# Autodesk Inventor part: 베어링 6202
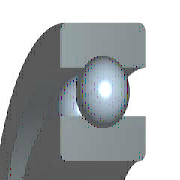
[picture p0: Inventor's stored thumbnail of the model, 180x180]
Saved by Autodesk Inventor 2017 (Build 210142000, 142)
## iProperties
IsCustomPart: 1
Created: 2015-12
Part Number: 베어링 6202
Material: 강철, 연강
Description: 깊은 그루브 볼 베어링
Document SubType Name: Modeling
Standard: KS B 2023
Designer: mdu
Standards Organization: KS
Language: ko-KR
Size Designation: 6202 - 15 x 35 x 11
Categories: <MemberInstance><Categories><Category DisplayName="샤프트 부품" InternalName="7f7aeb1f-a693-4053-b835-cee3144e0d98" Mnemonic="SHFT"><Category DisplayName="베어링" Inter
Density: 7.86 g/cm^3
Mass: 45.8725 g
Surface Area: 51.5584 cm^2
Volume: 5.83619 cm^3
Appearance: 노란색
Author: mdu
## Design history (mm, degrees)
sketch "스케치" dims "d0" = 5.2 (= -0.26 x WD + 0.26 x BD)
  geometry: L1 (2.9, 12.5)-(8.1, 12.5); L2 (5.5, 12.5)-(5.5, 9.9); L3 (5.5, 12.5)-(5.5, 15.1); L4 (3.568, 10.76)-(0, 10.76); L5 (0, 7.5)-(11, 7.5); L6 (3.568, 14.24)-(0, 14.24); L7 (0, 17.5)-(11, 17.5); L8 (11, 7.5)-(11, 10.76); L9 (7.432, 10.76)-(11, 10.76); L10 (7.432, 14.24)-(11, 14.24); L11 (11, 17.5)-(11, 14.24); L12 (-1.4, 0)-(8.4, 0) reference; L13 (0, -0.3)-(0, 5.3) reference
  constraints: 22 end point, 4 point on line, 2 collinear, 2 perpendicular, 2 symmetric about line, 1 midpoint, 1 parallel, 14 other
  dimensions: "d9" = 15 diameter of L5 L12 (= WD); "d11" = 35 diameter of L7 L12 (= BD); "d12" = 11 distance between parallel lines of L8 L13 (= KB); "d13" = 21.52 diameter of L9 L12 (= 0.326 x BD + 0.674 x WD)
revolve "본체" stored, may be unused: angle "d6" = 90 deg
revolve "볼" stored, may be unused: angle "d7" = 90 deg
pattern_circular "IDS_ARRAYBALL[SIMPL:T]" dims angle "d3" = 360 deg
body "Solid1"
fillet "모깎기1" dims "d1" = 0.6 (= KRS)
other parameters: "WD" = 15 [user parameter; used in 5 equation terms], "BD" = 35 [user parameter; used in 5 equation terms], "KB" = 11 [user parameter; used in 1 equation term], "KRS" = 0.6 [user parameter; used in 1 equation term], "d4" = 0, "d5" = 0, "d8" = 0, "d14" = 0, "d15" = 0, "BBA" = 0 [user parameter], "BC0" = 3750000 [user parameter], "BC" = 7800000 [user parameter], "BR" = 17.5 (= 0.5 x BD) [user parameter], "WR" = 7.5 (= 0.5 x WD) [user parameter]
